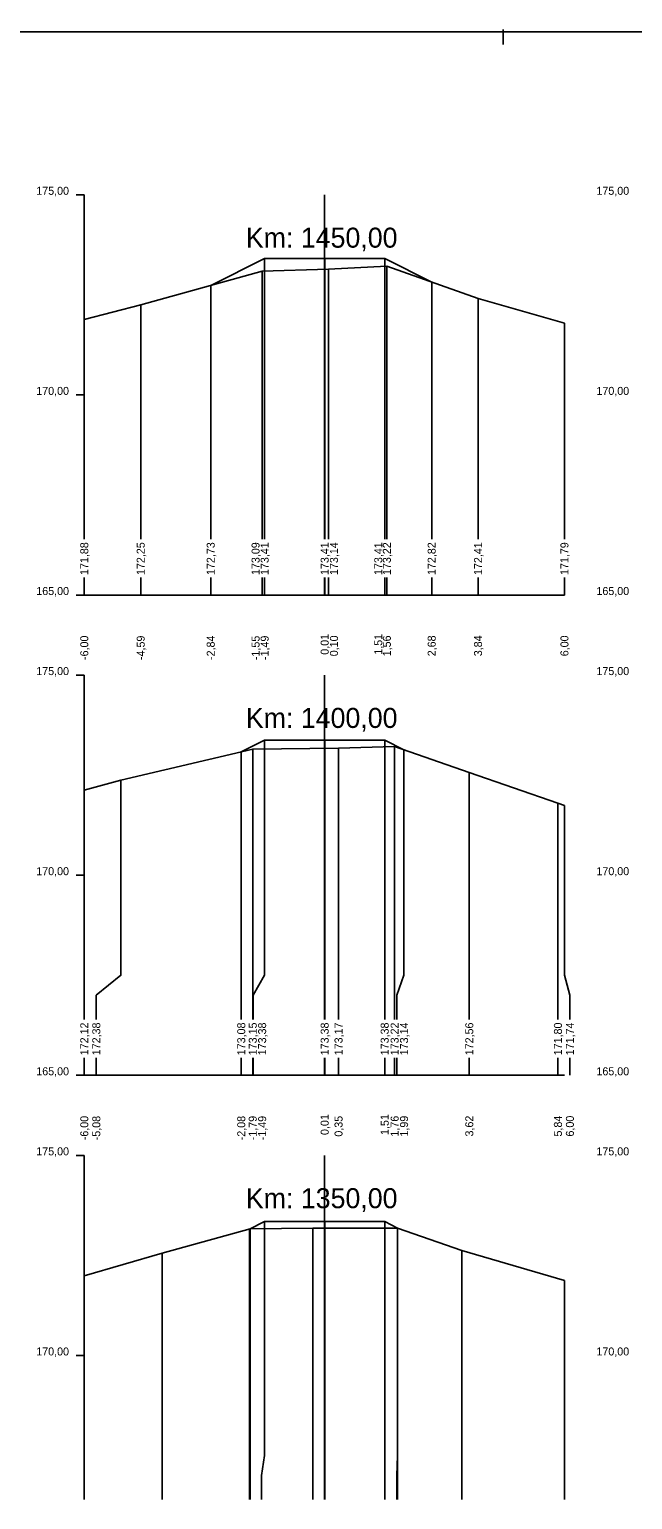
# Model space of a CAD drawing. Extents: x -614174 to -599765, y -1185887 to -1181080.
# Drawn here: x -601012.8 to -600997.72, y -1184419.94 to -1184383.21 of the extents above; entities that cross this region are included whole.
import ezdxf

# ---------------------------------------------------------------- set-up
doc = ezdxf.new("R2010")
doc.units = 0
for name, color, linetype in [('11', 7, 'Continuous'), ('16', 7, 'Continuous'), ('21', 7, 'Continuous'), ('28', 7, 'Continuous'), ('59', 7, 'Continuous'), ('8', 7, 'Continuous'), ('návrh', 7, 'Continuous')]:
    doc.layers.add(name, color=color, linetype=linetype)

msp = doc.modelspace()

# ---------------------------------------------------------------- linework, layer by layer
for points in [[(-601008.267, -1184389.608), (-601006.919, -1184388.934), (-601005.419, -1184388.934), (-601003.919, -1184388.934), (-601002.745, -1184389.521)], [(-601006.919, -1184388.934), (-601006.919, -1184388.934), (-601006.919, -1184388.934)], [(-601005.419, -1184388.934), (-601005.419, -1184388.934), (-601005.419, -1184388.934)], [(-601003.919, -1184388.934), (-601003.919, -1184388.934), (-601003.919, -1184388.934)], [(-601011.427, -1184390.46), (-601010.017, -1184390.093), (-601006.979, -1184389.25), (-601005.326, -1184389.197), (-601003.865, -1184389.126), (-601001.586, -1184389.93), (-600999.427, -1184390.549)], [(-601008.267, -1184389.607), (-601008.267, -1184389.608), (-601008.267, -1184389.608)], [(-601011.427, -1184402.22), (-601010.51, -1184401.966), (-601007.217, -1184401.191), (-601005.073, -1184401.168), (-601003.671, -1184401.125), (-601001.805, -1184401.777), (-600999.59, -1184402.543), (-600999.427, -1184402.598)], [(-601007.504, -1184401.258), (-601006.919, -1184400.966), (-601005.419, -1184400.966), (-601003.919, -1184400.966), (-601003.439, -1184401.206)], [(-601006.919, -1184400.966), (-601006.919, -1184400.966), (-601006.919, -1184400.966)], [(-601005.419, -1184400.966), (-601005.419, -1184400.966), (-601005.419, -1184400.966)], [(-601003.919, -1184400.966), (-601003.919, -1184400.966), (-601003.919, -1184400.966)], [(-601007.504, -1184401.258), (-601007.504, -1184401.258), (-601007.504, -1184401.258)], [(-601011.427, -1184414.354), (-601009.478, -1184413.789), (-601007.282, -1184413.182), (-601005.715, -1184413.165), (-601003.596, -1184413.16), (-601001.989, -1184413.722), (-600999.427, -1184414.468)], [(-601007.294, -1184413.185), (-601006.919, -1184412.998), (-601005.419, -1184412.998), (-601003.919, -1184412.998), (-601003.596, -1184413.16)], [(-601007.294, -1184413.185), (-601007.294, -1184413.185), (-601007.294, -1184413.185)], [(-601006.919, -1184412.998), (-601006.919, -1184412.998), (-601006.919, -1184412.998)], [(-601005.419, -1184412.998), (-601005.419, -1184412.998), (-601005.419, -1184412.998)], [(-601003.919, -1184412.998), (-601003.919, -1184412.998), (-601003.919, -1184412.998)]]:
    msp.add_lwpolyline(points)
at = {"layer": '11'}
for points in [[(-601006.919, -1184388.934), (-601006.919, -1184394.842), (-601006.919, -1184395.342), (-601006.919, -1184395.944)], [(-601005.419, -1184388.934), (-601005.419, -1184394.842), (-601005.419, -1184395.342), (-601005.419, -1184395.944)], [(-601003.919, -1184388.934), (-601003.919, -1184394.842), (-601003.919, -1184395.342), (-601003.919, -1184395.944)], [(-601006.979, -1184389.25), (-601006.979, -1184394.842), (-601006.979, -1184395.342), (-601006.979, -1184395.944)], [(-601005.326, -1184389.197), (-601005.326, -1184394.842), (-601005.326, -1184395.342), (-601005.326, -1184395.944)], [(-601003.865, -1184389.126), (-601003.865, -1184394.842), (-601003.865, -1184395.342), (-601003.865, -1184395.944)], [(-601008.267, -1184389.608), (-601008.267, -1184394.842), (-601008.267, -1184395.342), (-601008.267, -1184395.944)], [(-601002.745, -1184389.521), (-601002.745, -1184394.842), (-601002.745, -1184395.342), (-601002.745, -1184395.944)], [(-601010.017, -1184390.093), (-601010.017, -1184394.842), (-601010.017, -1184395.342), (-601010.017, -1184395.944)], [(-601001.586, -1184389.93), (-601001.586, -1184394.842), (-601001.586, -1184395.342), (-601001.586, -1184395.944)], [(-601011.427, -1184390.46), (-601011.427, -1184394.842), (-601011.427, -1184395.342), (-601011.427, -1184395.944)], [(-600999.427, -1184390.549), (-600999.427, -1184394.842), (-600999.427, -1184395.342), (-600999.427, -1184395.944)], [(-601011.427, -1184396.902), (-601011.427, -1184397.342)], [(-601010.017, -1184396.902), (-601010.017, -1184397.342)], [(-601008.267, -1184396.902), (-601008.267, -1184397.342)], [(-601006.979, -1184396.902), (-601006.979, -1184397.342)], [(-601006.919, -1184396.902), (-601006.919, -1184397.342)], [(-601005.419, -1184396.902), (-601005.419, -1184397.342)], [(-601005.326, -1184396.902), (-601005.326, -1184397.342)], [(-601003.919, -1184396.902), (-601003.919, -1184397.342)], [(-601003.865, -1184396.902), (-601003.865, -1184397.342)], [(-601002.745, -1184396.902), (-601002.745, -1184397.342)], [(-601001.586, -1184396.902), (-601001.586, -1184397.342)], [(-600999.427, -1184396.902), (-600999.427, -1184397.342)], [(-601006.919, -1184400.966), (-601006.919, -1184406.842), (-601007.204, -1184407.342), (-601007.204, -1184407.944)], [(-601005.419, -1184400.966), (-601005.419, -1184406.842), (-601005.419, -1184407.342), (-601005.419, -1184407.944)], [(-601003.919, -1184400.966), (-601003.919, -1184406.842), (-601003.919, -1184407.342), (-601003.919, -1184407.944)], [(-601003.671, -1184401.125), (-601003.671, -1184406.842), (-601003.671, -1184407.342), (-601003.671, -1184407.944)], [(-601007.504, -1184401.258), (-601007.504, -1184406.842), (-601007.504, -1184407.342), (-601007.504, -1184407.944)], [(-601007.217, -1184401.191), (-601007.217, -1184406.842), (-601007.217, -1184407.342), (-601007.217, -1184407.944)], [(-601005.073, -1184401.168), (-601005.073, -1184406.842), (-601005.073, -1184407.342), (-601005.073, -1184407.944)], [(-601003.439, -1184401.206), (-601003.439, -1184406.842), (-601003.619, -1184407.342), (-601003.619, -1184407.944)], [(-601001.805, -1184401.777), (-601001.805, -1184406.842), (-601001.805, -1184407.342), (-601001.805, -1184407.944)], [(-601011.427, -1184402.22), (-601011.427, -1184406.842), (-601011.427, -1184407.342), (-601011.427, -1184407.944)], [(-601010.51, -1184401.966), (-601010.51, -1184406.842), (-601011.127, -1184407.342), (-601011.127, -1184407.944)], [(-600999.59, -1184402.543), (-600999.59, -1184406.842), (-600999.59, -1184407.342), (-600999.59, -1184407.944)], [(-600999.427, -1184402.598), (-600999.427, -1184406.842), (-600999.29, -1184407.342), (-600999.29, -1184407.944)], [(-601011.427, -1184408.902), (-601011.427, -1184409.342)], [(-601011.127, -1184408.902), (-601011.127, -1184409.342)], [(-601007.504, -1184408.902), (-601007.504, -1184409.342)], [(-601007.217, -1184408.902), (-601007.217, -1184409.342)], [(-601007.204, -1184408.902), (-601007.204, -1184409.342)], [(-601005.419, -1184408.902), (-601005.419, -1184409.342)], [(-601005.073, -1184408.902), (-601005.073, -1184409.342)], [(-601003.919, -1184408.902), (-601003.919, -1184409.342)], [(-601003.671, -1184408.902), (-601003.671, -1184409.342)], [(-601003.619, -1184408.902), (-601003.619, -1184409.342)], [(-601001.805, -1184408.902), (-601001.805, -1184409.342)], [(-600999.59, -1184408.902), (-600999.59, -1184409.342)], [(-600999.29, -1184408.902), (-600999.29, -1184409.342)], [(-601007.294, -1184413.185), (-601007.294, -1184418.842), (-601007.294, -1184419.342), (-601007.294, -1184419.944)], [(-601007.282, -1184413.182), (-601007.282, -1184418.842), (-601007.282, -1184419.342), (-601007.282, -1184419.944)], [(-601006.919, -1184412.998), (-601006.919, -1184418.842), (-601006.994, -1184419.342), (-601006.994, -1184419.944)], [(-601005.715, -1184413.165), (-601005.715, -1184418.842), (-601005.715, -1184419.342), (-601005.715, -1184419.944)], [(-601005.419, -1184412.998), (-601005.419, -1184418.842), (-601005.419, -1184419.342), (-601005.419, -1184419.944)], [(-601003.919, -1184412.998), (-601003.919, -1184418.842), (-601003.919, -1184419.342), (-601003.919, -1184419.944)], [(-601003.596, -1184413.16), (-601003.596, -1184418.842), (-601003.619, -1184419.342), (-601003.619, -1184419.944)], [(-601003.596, -1184413.16), (-601003.596, -1184418.842), (-601003.596, -1184419.342), (-601003.596, -1184419.944)], [(-601009.478, -1184413.789), (-601009.478, -1184418.842), (-601009.478, -1184419.342), (-601009.478, -1184419.944)], [(-601001.989, -1184413.722), (-601001.989, -1184418.842), (-601001.989, -1184419.342), (-601001.989, -1184419.944)], [(-601011.427, -1184414.354), (-601011.427, -1184418.842), (-601011.427, -1184419.342), (-601011.427, -1184419.944)], [(-600999.427, -1184414.468), (-600999.427, -1184418.842), (-600999.427, -1184419.342), (-600999.427, -1184419.944)]]:
    msp.add_lwpolyline(points, dxfattribs=at)
at = {"layer": '16'}
for p, q in [((-601011.427, -1184397.342), (-600999.427, -1184397.342)), ((-601011.427, -1184409.342), (-600999.427, -1184409.342))]:
    msp.add_line(p, q, dxfattribs=at)
for points in [[(-601002.745, -1184389.521), (-601002.745, -1184389.521), (-601002.745, -1184389.521)], [(-601003.44, -1184401.206), (-601003.439, -1184401.206), (-601003.439, -1184401.206)], [(-601003.596, -1184413.16), (-601003.596, -1184413.16), (-601003.596, -1184413.16)]]:
    msp.add_lwpolyline(points, dxfattribs=at)
at = {"layer": '21'}
for p, q in [((-601011.627, -1184387.342), (-601011.427, -1184387.342)), ((-601011.627, -1184392.342), (-601011.427, -1184392.342)), ((-601011.627, -1184397.342), (-601011.427, -1184397.342)), ((-601011.627, -1184399.342), (-601011.427, -1184399.342)), ((-601011.627, -1184404.342), (-601011.427, -1184404.342)), ((-601011.627, -1184409.342), (-601011.427, -1184409.342)), ((-601011.627, -1184411.342), (-601011.427, -1184411.342)), ((-601011.627, -1184416.342), (-601011.427, -1184416.342))]:
    msp.add_line(p, q, dxfattribs=at)
at = {"layer": '28'}
for p, q in [((-601005.427, -1184395.944), (-601005.427, -1184387.342)), ((-601005.427, -1184397.342), (-601005.427, -1184396.902)), ((-601005.427, -1184407.944), (-601005.427, -1184399.342)), ((-601005.427, -1184409.342), (-601005.427, -1184408.902)), ((-601005.427, -1184419.944), (-601005.427, -1184411.342))]:
    msp.add_line(p, q, dxfattribs=at)
at = {"layer": '8'}
for p, q in [((-601011.427, -1184395.944), (-601011.427, -1184387.342)), ((-601011.427, -1184397.342), (-601011.427, -1184396.902)), ((-601011.427, -1184407.944), (-601011.427, -1184399.342)), ((-601011.427, -1184409.342), (-601011.427, -1184408.902)), ((-601011.427, -1184419.944), (-601011.427, -1184411.342))]:
    msp.add_line(p, q, dxfattribs=at)
at = {"layer": 'návrh'}
for p, q in [((-601084.957, -1184383.271), (-600937.957, -1184383.271)), ((-601000.957, -1184383.59), (-601000.957, -1184383.209))]:
    msp.add_line(p, q, dxfattribs=at)

# ---------------------------------------------------------------- texts
at = {"layer": '16'}
for s, p in [('171,88', (-601011.327, -1184396.842)), ('172,25', (-601009.917, -1184396.842)), ('172,73', (-601008.167, -1184396.842)), ('173,09', (-601007.046, -1184396.842)), ('173,41', (-601006.819, -1184396.842)), ('173,41', (-601005.319, -1184396.842)), ('173,14', (-601005.087, -1184396.842)), ('173,41', (-601003.979, -1184396.842)), ('173,22', (-601003.765, -1184396.842)), ('172,82', (-601002.645, -1184396.842)), ('172,41', (-601001.486, -1184396.842)), ('171,79', (-600999.327, -1184396.842)), ('172,12', (-601011.327, -1184408.842)), ('172,38', (-601011.027, -1184408.842)), ('173,08', (-601007.404, -1184408.842)), ('173,15', (-601007.117, -1184408.842)), ('173,38', (-601006.882, -1184408.842)), ('173,38', (-601005.319, -1184408.842)), ('173,17', (-601004.973, -1184408.842)), ('173,38', (-601003.819, -1184408.842)), ('173,22', (-601003.571, -1184408.842)), ('173,14', (-601003.335, -1184408.842)), ('172,56', (-601001.705, -1184408.842)), ('171,80', (-600999.49, -1184408.842)), ('171,74', (-600999.19, -1184408.842))]:
    msp.add_text(s, height=0.2, rotation=90, dxfattribs=at).set_placement(p)
at = {"layer": '21'}
for s, p in [('175,00', (-601012.627, -1184387.342)), ('175,00', (-600998.627, -1184387.342)), ('170,00', (-601012.627, -1184392.342)), ('170,00', (-600998.627, -1184392.342)), ('165,00', (-601012.627, -1184397.342)), ('165,00', (-600998.627, -1184397.342)), ('175,00', (-601012.627, -1184399.342)), ('175,00', (-600998.627, -1184399.342)), ('170,00', (-601012.627, -1184404.342)), ('170,00', (-600998.627, -1184404.342)), ('165,00', (-601012.627, -1184409.342)), ('165,00', (-600998.627, -1184409.342)), ('175,00', (-601012.627, -1184411.342)), ('175,00', (-600998.627, -1184411.342)), ('170,00', (-601012.627, -1184416.342)), ('170,00', (-600998.627, -1184416.342))]:
    msp.add_text(s, height=0.2, dxfattribs=at).set_placement(p)
at = {"layer": '28'}
for s, p in [('Km: 1450,00', (-601007.39, -1184388.663)), ('Km: 1400,00', (-601007.39, -1184400.663)), ('Km: 1350,00', (-601007.39, -1184412.663))]:
    msp.add_text(s, height=0.5, dxfattribs=at).set_placement(p)
at = {"layer": '59'}
for s, p in [('-6,00', (-601011.327, -1184398.965)), ('-4,59', (-601009.917, -1184398.966)), ('-2,84', (-601008.167, -1184398.965)), ('-1,55', (-601007.046, -1184398.968)), ('-1,49', (-601006.819, -1184398.966)), ('0,01', (-601005.319, -1184398.834)), ('0,10', (-601005.087, -1184398.872)), ('1,51', (-601003.979, -1184398.834)), ('1,56', (-601003.765, -1184398.873)), ('2,68', (-601002.645, -1184398.873)), ('3,84', (-601001.486, -1184398.872)), ('6,00', (-600999.327, -1184398.872)), ('0,01', (-601005.319, -1184410.834)), ('1,51', (-601003.819, -1184410.834)), ('-6,00', (-601011.327, -1184410.965)), ('-5,08', (-601011.027, -1184410.966)), ('-2,08', (-601007.404, -1184410.966)), ('-1,79', (-601007.117, -1184410.966)), ('-1,49', (-601006.882, -1184410.966)), ('0,35', (-601004.973, -1184410.875)), ('1,76', (-601003.571, -1184410.873)), ('1,99', (-601003.335, -1184410.873)), ('3,62', (-601001.705, -1184410.871)), ('5,84', (-600999.49, -1184410.872)), ('6,00', (-600999.19, -1184410.872))]:
    msp.add_text(s, height=0.2, rotation=90, dxfattribs=at).set_placement(p)

doc.saveas('drawing.dxf')
